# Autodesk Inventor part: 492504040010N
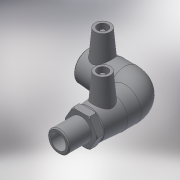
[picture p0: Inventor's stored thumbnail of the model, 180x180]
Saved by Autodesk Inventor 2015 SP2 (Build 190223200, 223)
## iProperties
Created: 2017-06
Part Number: 492504040010N
Material: Generic
Description: PLASSON 90° ELBOW MALE TRANSITION 40 x 1"
Document SubType Name: Modeling
Designer: KIM
Mass: 222.696 g
Surface Area: 514.71 cm^2
Volume: 222.696 cm^3
Density: 1 g/cm^3
Appearance: Default
Author: KIM
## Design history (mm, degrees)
derived "492504.ipt"
feature "Solid1::492504.ipt"
tag "TaggingFeature1"
body "Solid1"
other parameters: "d2" = 56, "d4" = 31, "d5" = 50.4, "d8" = 168 deg, "d10" = 17.6, "d11" = 5.86667, "d29" = 47, "d30" = 15, "d31" = 51.15, "d34" = 5 deg, "d41" = 4, "d42" = 14, "d43" = 0, "d48" = 65, "d50" = 34, "d51" = 17.6, "d52" = 44, "d54" = 90 deg, "d58" = 44, "d59" = 0, "d61" = 90 deg, "d86" = 3, "d87" = 0, "d93" = 0.1, "d94" = 12.25, "d95" = 33.249, "d96" = 23.2743, "d97" = 22, "d98" = 49, "d99" = 56, "d100" = 44.1, "d102" = 2, "d106" = 0, "L_" = 142, "L_1" = 44, "D_" = 22, "A_" = 47, "d_2" = 12, "L_2" = 49, "D_1" = 56, "R_" = 33.249
